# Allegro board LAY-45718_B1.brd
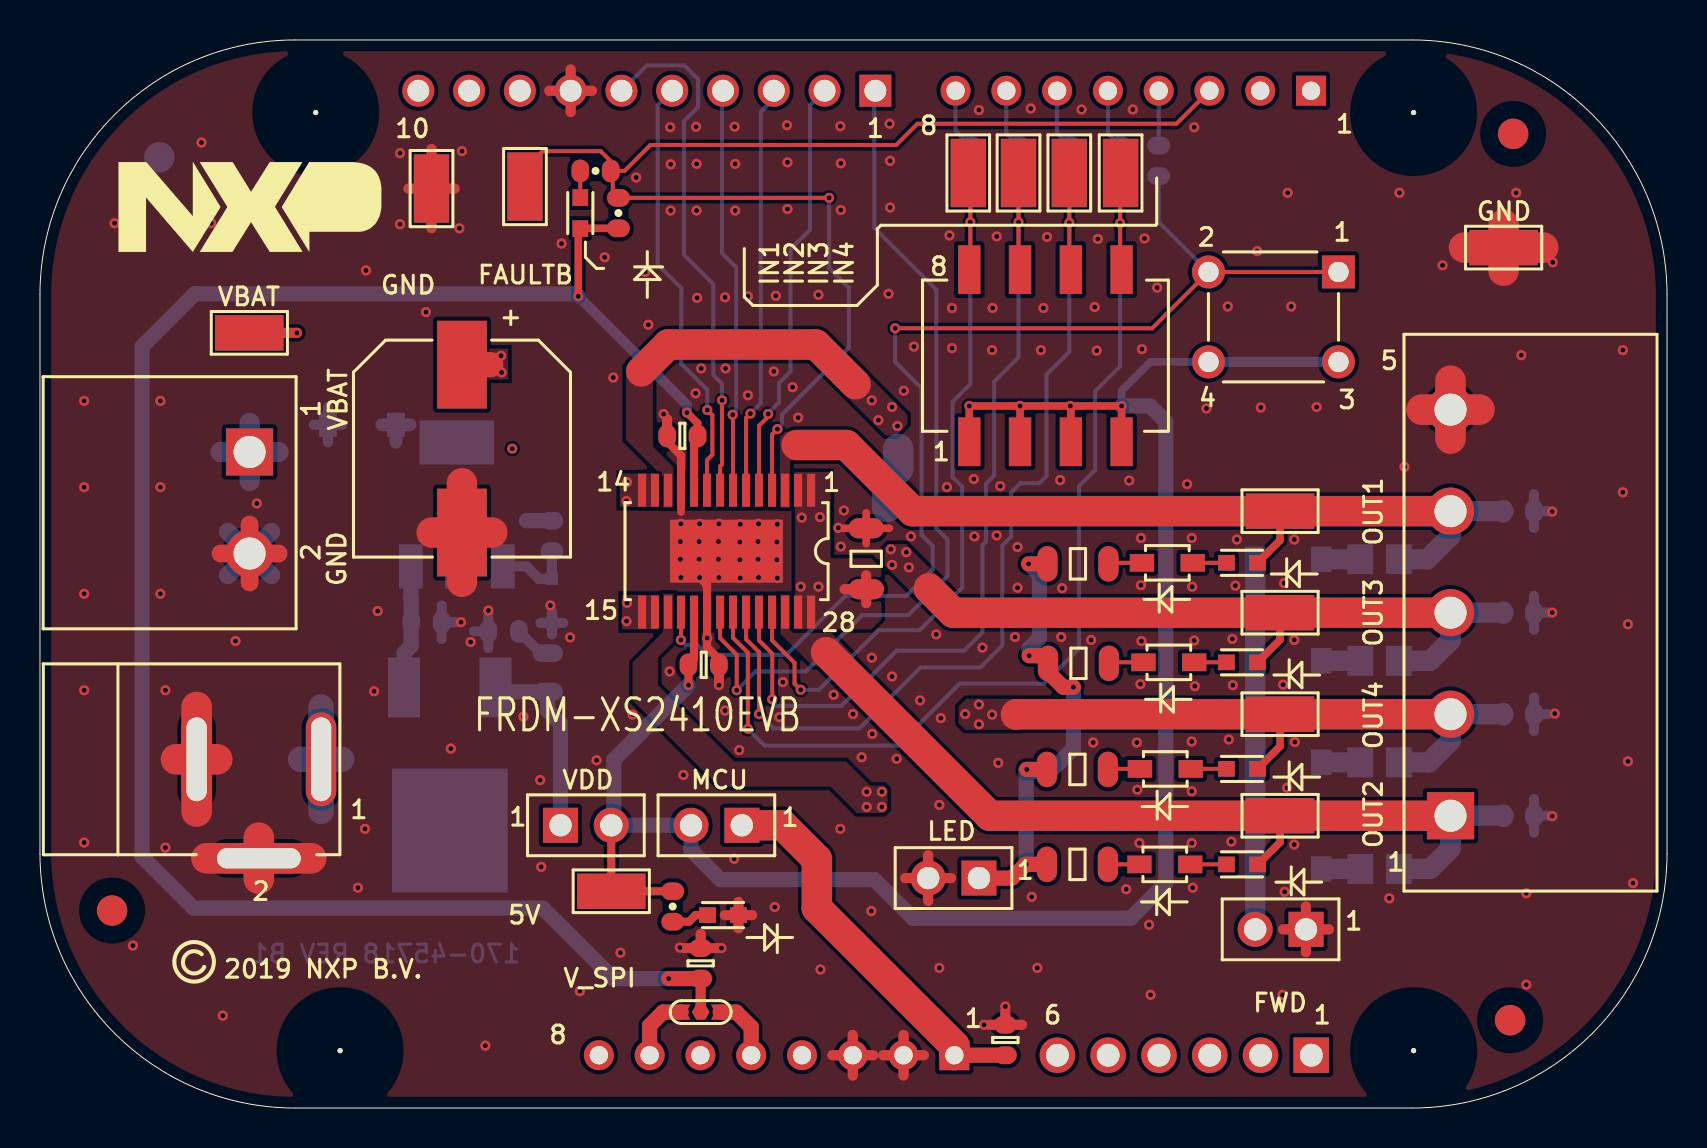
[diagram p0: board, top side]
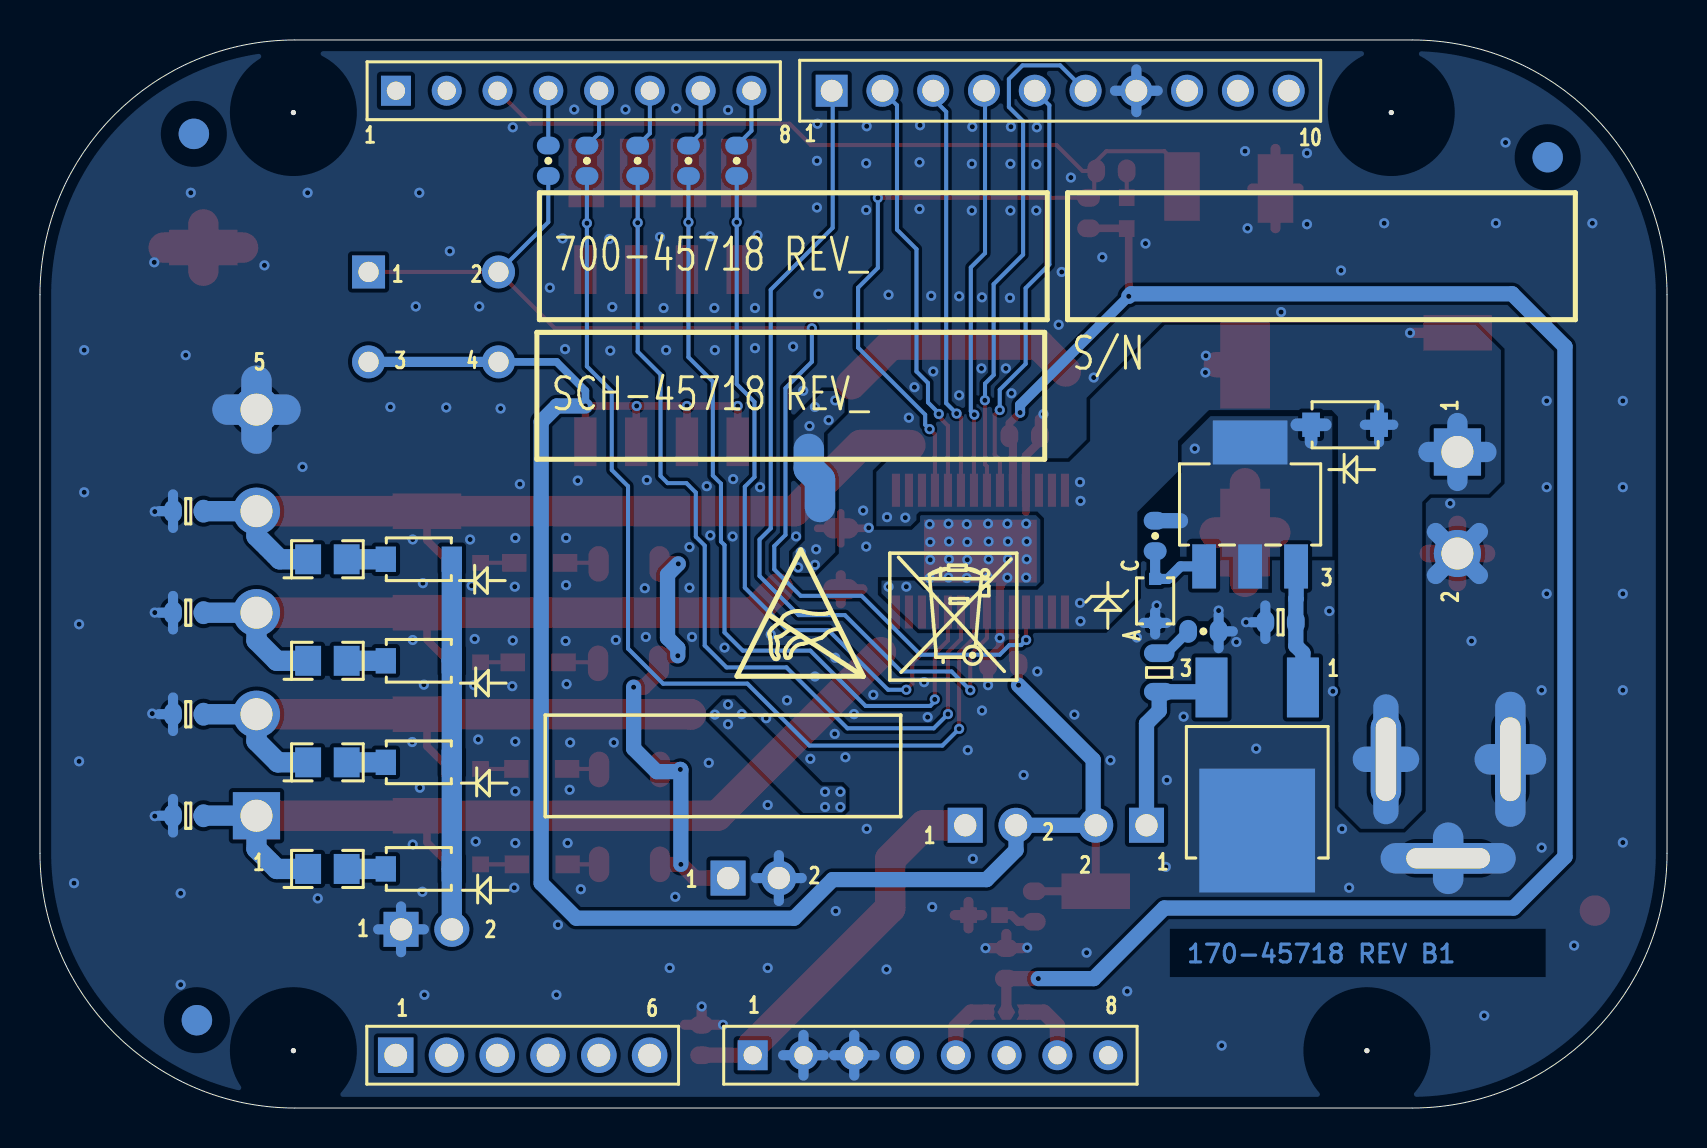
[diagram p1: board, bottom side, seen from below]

Outline 81.38 x 53.44 mm; copper layers: TOP, BOTTOM. Coordinates in mm from the lower left corner of the outline.
Outline path: 0,40.69 arc(3.73,49.71) 12.75,53.44 68.63,53.44 arc(77.65,49.71) 81.38,40.69 81.38,12.75 arc(77.65,3.73) 68.63,0 12.75,0 arc(3.73,3.73) 0,12.75 0,40.69

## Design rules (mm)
constraint set DEFAULT: min track width 0.127
net group POWER: nets 5V AGND OUT1 OUT2 V_MCU V_SPI VOUT_LDO

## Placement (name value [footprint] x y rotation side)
C1  0.1uF  [CC1206_OV]  41.33 27.48 90 top
C2  100UF  [CAP_10DIA_10P5]  21.11 32.99 270 top
C3  0.1uF  [CC0603_OV]  32.13 33.63 180 top
C4  0.1uF  [CC0603_OV]  33.2 22.17 0 top
C5  0.01uF  [CC0603_OV]  73.96 29.86 0 bottom
C6  0.33UF  [CC0603_OV]  19.33 24.31 0 bottom
C7  10UF  [CC0805_OV]  25.4 21.79 90 bottom
C8  0.01uF  [CC0603_OV]  73.96 14.62 0 bottom
C9  0.01uF  [CC0603_OV]  73.96 24.78 0 bottom
C10  0.01uF  [CC0603_OV]  73.96 19.7 0 bottom
C11  0.1uF  [CC0603_OV]  33.05 7.24 90 top
C12  0.1uF  [CC0603_OV]  48.29 3.4 90 top
D1  CMMR1U-02  [SOD-123F]  16.1 34.19 0 bottom
D2  RF071M2STR  [SOD123]  62.43 27.46 180 bottom
D3  RF071M2STR  [SOD123]  62.43 11.96 180 bottom
D4  RF071M2STR  [SOD123]  62.43 22.38 180 bottom
D5  RF071M2STR  [SOD123]  62.43 17.3 180 bottom
D6  GDZ15B-E3-08  [SOD323_B]  25.6 25.37 270 bottom
D7  RED  [LED_0603]  27.03 44.78 90 top
D8  LED GREEN  [LED_0603]  60.12 12.19 180 top
D9  LED GREEN  [LED_0603]  60.12 27.28 180 top
D10  LED GREEN  [LED_0603]  60.12 22.3 180 top
D11  LED GREEN  [LED_0603]  60.12 16.97 180 top
D12  LED GREEN  [LED_0603]  34.16 9.65 0 top
D13  1PS76SB70  [SOD323]  56.39 27.28 270 top
D14  1PS76SB70  [SOD323]  56.26 12.19 270 top
D15  1PS76SB70  [SOD323]  56.46 22.3 270 top
D16  1PS76SB70  [SOD323]  56.29 16.97 270 top
J3  CON_1X2  [CON2_5P08_12P26X12_RA_TH]  10.48 32.83 270 top
J4  OSTOQ055451  [CON5_5P08_27P5X12_RA_TH]  70.55 14.62 90 top
J5  DC_POWER_JACK  [CONN_DC_POWER_3P]  14.06 17.45 270 top
J8  HDR 1X8  [HDR1X8_2P54_TH]  63.58 50.9 90 bottom
J9  HDR 1X8  [HDR1X8_2P54_TH]  45.73 2.64 90 bottom
J10  HDR 1X10  [HDR_1X10_100_TH]  41.78 50.9 90 bottom
J11  HDR1X2  [HDR1X2_5P48X2P69]  63.32 8.94 180 top
J12  HDR1X2  [HDR1X2_5P48X2P69]  35.1 14.15 180 top
J13  HDR1X2  [HDR1X2_5P48X2P69]  26.04 14.15 0 top
J14  HDR1X2  [HDR1X2_5P48X2P69]  46.96 11.51 180 top
JP1  HDR 1X6  [HDR106_B]  63.59 2.64 90 bottom
NOREF  -  [unnamed]  3.61 9.88 0 top
NOREF#2  -  [#2]  44.42 11.51 0 top
NOREF#3  -  [#2]  -378.12 187.91 0 top
NOREF#4  -  [#2]  32.07 4.8 0 top
NOREF#5  -  [#2]  18.92 50.9 0 top
NOREF#6  -  [#2]  80.7 23.33 0 top
NOREF#7  -  [#2]  42.05 15.49 90 top
NOREF#8  -  [#2]  64.79 10.29 0 top
NOREF#9  -  [#2]  70.55 14.62 0 top
NOREF#10  -  [#2]  32.56 14.15 0 top
NOREF#11  -  [#2]  68.63 0.05 90 top
NOREF#12  -  [#2]  25.6 24.27 90 top
NOREF#13  -  [#2]  39.24 50.9 0 top
NOREF#14  -  [#2]  36.57 15.49 0 top
NOREF#15  -  [#2]  28.3 26.35 90 top
NOREF#16  -  [#2]  70.55 14.62 90 top
NOREF#17  -  [#2]  0.33 36.42 90 top
NOREF#18  -  [#2]  -13.94 -50.83 0 top
NOREF#19  -  [#2]  7.71 7.29 0 top
NOREF#20  -  [#2]  21.11 28.79 90 top
NOREF#21  -  [#2]  10.48 32.83 90 top
NOREF#22  -  [#2]  43.2 23.86 90 top
NOREF#23  -  [#2]  26.04 14.15 0 top
NOREF#24  -  [#2]  0.33 48.72 0 top
NOREF#25  -  [#2]  70.55 14.62 90 top
NOREF#26  -  [#2]  53.91 12.85 90 top
NOREF#27  -  [#2]  32.07 4.8 0 top
NOREF#28  -  [#2]  48.43 12.85 0 top
NOREF#29  -  [#2]  60.78 8.94 0 top
NOREF#30  -  [#2]  70.27 10.29 90 top
NOREF#31  -  [#2]  -404.15 -337.24 0 top
NOREF#32  -  [#2]  3.94 42.84 0 top
NOREF#33  -  [#2]  43.2 23.86 0 top
NOREF#34  -  [#2]  10.48 27.75 90 top
NOREF#35  -  [#2]  80.7 11.03 90 top
NOREF#36  -  [#2]  70.55 34.94 90 top
NOREF#37  -  [#2]  -12.74 -34.06 0 top
NOREF#38  -  [#2]  24.57 12.8 0 top
NOREF#39  -  [#2]  0.33 48.72 0 top
NOREF#40  -  [#2]  70.55 34.94 0 top
NOREF#41  -  [#2]  26.35 26.35 0 top
NOREF#42  -  [#2]  30.05 12.8 90 top
NOREF#43  -  [unnamed]  73.69 48.74 0 top
NOREF#44  -  [unnamed]  73.53 4.39 0 top
NOREF#45  -  [#2]  0.05 53.39 0 top
NOREF#46  -  [#2]  56.11 14.58 180 bottom
NOREF#47  -  [unnamed]  73.69 48.74 180 bottom
NOREF#48  -  [unnamed]  5.97 47.57 180 bottom
NOREF#49  -  [#2]  38.87 21.41 180 bottom
NOREF#50  -  [#2]  56.53 32.46 180 bottom
NOREF#51  -  [unnamed]  68.71 2.87 180 bottom
NOREF#52  -  [unnamed]  73.53 4.39 180 bottom
NOREF#53  -  [#2]  29.98 39.45 180 bottom
NOREF#54  -  [unnamed]  13.79 49.81 180 bottom
NOREF#55  -  [unnamed]  15.01 2.87 180 bottom
NOREF#56  -  [unnamed]  68.71 49.81 180 bottom
NOREF#57  -  [#2]  29.73 24.97 180 bottom
NOREF#58  -  [#2]  56.4 39.45 180 bottom
Q1  FZT692B  [SOT223]  20.85 30.2 180 bottom
R1  10K  [RC0603_OV]  25.6 28.63 270 bottom
R2  1.0K  [RC0603_OV]  31.65 10.08 270 top
R3  1.0K  [RC0603_OV]  27.79 46.89 0 top
R4  10K  [RC0603_OV]  55.96 47.4 270 bottom
R5  10K  [RC0603_OV]  54.03 47.4 270 bottom
R6  4.99K  [RC1206_OV]  51.92 27.23 180 top
R7  4.99K  [RC1206_OV]  51.89 12.19 180 top
R8  4.99K  [RC1206_OV]  51.94 22.25 180 top
R9  4.99K  [RC1206_OV]  51.89 16.94 180 top
R10  10K  [RC0603_OV]  51.49 47.4 270 bottom
R11  10K  [RC0603_OV]  48.95 47.4 270 bottom
R12  10K  [RC0603_OV]  46.53 47.4 270 bottom
R13  10K  [RC0603_OV]  28.93 44.78 90 top
R14  3 PIN 0402 JUMPER  [3PIN_0402_SOLDER_BLOB_JUMPER]  33.05 4.8 0 top
R15  0  [RC0603_OV]  23.19 23.85 180 bottom
SH1  SOLDER SHORT  [SH0805]  67.01 27.46 180 bottom
SH2  SOLDER SHORT  [SH0805]  67.01 11.96 180 bottom
SH3  SOLDER SHORT  [SH0805]  67.01 22.38 180 bottom
SH4  SOLDER SHORT  [SH0805]  67.01 17.3 180 bottom
SW1  TL1105AF100Q  [SW4_6X6_TH]  64.95 41.83 180 top
SW2  SW_DIP-4/SM  [DIP-SMT4]  50.29 37.64 90 top
TP1  TESTLOOP  [TESTPOINT_135_070MIL]  62.03 29.86 0 top
TP2  TESTLOOP  [TESTPOINT_135_070MIL]  62.03 14.62 0 top
TP3  TESTLOOP  [TESTPOINT_135_070MIL]  62.03 24.78 0 top
TP4  TESTLOOP  [TESTPOINT_135_070MIL]  62.03 19.7 0 top
TP5  TESTLOOP  [TESTPOINT_135_070MIL]  46.43 46.79 90 top
TP6  TESTLOOP  [TESTPOINT_135_070MIL]  19.58 46.01 90 top
TP7  TESTLOOP  [TESTPOINT_135_070MIL]  73.21 43.05 0 top
TP8  TESTLOOP  [TESTPOINT_135_070MIL]  10.47 38.79 0 top
TP9  TESTLOOP  [TESTPOINT_135_070MIL]  48.95 46.79 90 top
TP10  TESTLOOP  [TESTPOINT_135_070MIL]  24.26 46.11 90 top
TP11  TESTLOOP  [TESTPOINT_135_070MIL]  51.49 46.79 90 top
TP12  TESTLOOP  [TESTPOINT_135_070MIL]  28.57 10.85 0 top
TP13  TESTLOOP  [TESTPOINT_135_070MIL]  54.05 46.79 90 top
U1  MC33XS2410EL  [TSSOP28_TAB124X222]  34.34 27.86 270 top
U2  LP2950CP  [DPAK_CASE_369C-01]  20.5 15.16 0 bottom

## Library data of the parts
C1 C3-C12 = CAP_NP
C2 = CAP_POL
D1-D5 = DIODE
D6 = ZDIODE
D7-D12 = LED
D13-D16 = DIODE_SCHTKY
J3 = CONN_PLUG_1X2_M
J4 = CONN_HDR_5X1
J5 = DC_POWER_JACK_3
J8 J9 = CONN_HDR_8X1
J10 = HDR-1X10
J11-J14 = CONN_HDR_2X1
JP1 = CONN_PLUG_1X6_M
Q1 = TRAN_NPN_SOT223
R1-R13 R15 = RES
R14 = 3_Pad_Solder_Blob_Jumper
SH1-SH4 = RES_SHORT-2
SW1 = SW_PB_ESW
SW2 = SW_DIP-4_SM
TP1-TP13 = TESTLOOP
U1 = MC33XS4210_28P
U2 = MC7805

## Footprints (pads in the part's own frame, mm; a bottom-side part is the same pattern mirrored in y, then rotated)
3PIN_0402_SOLDER_BLOB_JUMPER
  custom 0.191x0.191 smd: 1(0,0) 2(0.978,0) 3(-0.978,0)
CAP_10DIA_10P5
  rect 4.394x2.489 smd: 1(-4.2,0) 2(4.2,0)
CC0603_OV
  oval 0.889x1.143 smd: 1(-0.762,0) 2(0.762,0)
CC0805_OV
  oval 0.889x1.524 smd: 1(-0.965,0) 2(0.965,0)
CC1206_OV
  oval 1.016x1.778 smd: 1(-1.524,0) 2(1.524,0)
CON2_5P08_12P26X12_RA_TH
  rect 2.362x2.362 hole 1.6: 1(0,0)
  round 2.362 hole 1.6: 2(5.08,0)
CON5_5P08_27P5X12_RA_TH
  rect 2.362x2.362 hole 1.6: 1(0,0)
  round 2.362 hole 1.6: 2(5.08,0) 3(10.16,0) 4(15.24,0) 5(20.32,0)
CONN_DC_POWER_3P
  oval 4.699x1.524 hole 4.191x1.016: 1(0,0) 3(0,-6.223)
  oval 1.524x4.699 hole 1.016x4.191: 2(4.953,-3.111)
DIP-SMT4
  rect 2.438x1.118 smd: 1(-4.305,3.81) 2(-4.305,1.27) 3(-4.305,-1.27) 4(-4.305,-3.81) 5(4.305,-3.81) 6(4.305,-1.27) 7(4.305,1.27) 8(4.305,3.81)
DPAK_CASE_369C-01
  rect 1.6x2.997 smd: 1(-2.286,-5.88) 3(2.286,-5.88)
  rect 5.791x6.198 smd: 4(0,1.283)
HDR1X2_5P48X2P69
  rect 1.753x1.753 hole 1.118: 1(0,0)
  round 1.753 hole 1.118: 2(2.54,0)
HDR1X8_2P54_TH
  rect 1.499x1.499 hole 0.914: 1(0,0)
  round 1.499 hole 0.914: 2(0,-2.54) 3(0,-5.08) 4(0,-7.62) 5(0,-10.16) 6(0,-12.7) 7(0,-15.24) 8(0,-17.78)
HDR106_B
  rect 1.778x1.778 hole 1.143: 1(0,0)
  round 1.778 hole 1.143: 2(0,-2.54) 3(0,-5.08) 4(0,-7.62) 5(0,-10.16) 6(0,-12.7)
HDR_1X10_100_TH
  rect 1.6x1.6 hole 1.092: 1(0,0)
  round 1.6 hole 1.092: 2(0,-2.54) 3(0,-5.08) 4(0,-7.62) 5(0,-10.16) 6(0,-12.7) 7(0,-15.24) 8(0,-17.78) 9(0,-20.32) 10(0,-22.86)
LED_0603
  rect 0.838x0.787 smd: A(-0.775,0) C(0.775,0)
RC0603_OV
  oval 0.889x1.143 smd: 1(-0.762,0) 2(0.762,0)
RC1206_OV
  oval 1.016x1.778 smd: 1(-1.524,0) 2(1.524,0)
SH0805
  rect 1.295x1.499 smd: 1(-0.965,0) 2(0.965,0)
SOD123
  rect 1.016x1.27 smd: A(1.651,0) C(-1.651,0)
SOD323
  rect 0.889x1.219 smd: A(0,1.27) C(0,-1.27)
SOD323_B
  rect 0.61x0.61 smd: A(1.1,0) C(-1.1,0)
SOD-123F
  rect 0.889x1.219 smd: A(-1.7,0) C(1.7,0)
SOT223
  rect 1.194x2.21 smd: 1(-2.3,-3.1) 2(0,-3.1) 3(2.3,-3.1)
  rect 3.734x2.21 smd: 4(0,3.1)
SW4_6X6_TH
  rect 1.651x1.651 hole 1.016: 1(0,0)
  round 1.651 hole 1.016: 2(6.5,0) 3(0,4.5) 4(6.5,4.5)
TESTPOINT_135_070MIL
  rect 3.429x1.778 smd: 1(0,0)
TSSOP28_TAB124X222
  rect 1.651x0.406 smd: 1(-3.048,4.227) 2(-3.048,3.576) 3(-3.048,2.926) 4(-3.048,2.276) 5(-3.048,1.626) 6(-3.048,0.975) 7(-3.048,0.325) 8(-3.048,-0.325) 9(-3.048,-0.975) 10(-3.048,-1.626) 11(-3.048,-2.276) 12(-3.048,-2.926) 13(-3.048,-3.576) 14(-3.048,-4.227) 15(3.048,-4.227) 16(3.048,-3.576) 17(3.048,-2.926) 18(3.048,-2.276) 19(3.048,-1.626) 20(3.048,-0.975) 21(3.048,-0.325) 22(3.048,0.325) 23(3.048,0.975) 24(3.048,1.626) 25(3.048,2.276) 26(3.048,2.926) 27(3.048,3.576) 28(3.048,4.227)
  rect 3.15x5.639 smd: 29(0,0)
unnamed
  round 1.524 smd: (0,0)

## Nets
5V: C4.1 J12.2 J13.2 R2.1 SW1.3 SW1.4(B2) SW2.1 SW2.2 SW2.3 SW2.4 TP12.1(PIN1) U1.19
AGND: C1.2 C2.2 C3.2 C4.2 C5.2 C6.2 C8.2 C9.2 C10.2 C11.2 C12.2 D6.A D12.C(CATHODE) J3.2 J4.5 J5.2 J5.3 J9.2 J9.3 J10.7 J11.1 J14.2 R15.2 TP6.1(PIN1) TP7.1(PIN1) U1.11 U1.20 U1.29 U2.4
VBAT: C1.1 C2.1 D1.A J3.1 J5.1 TP8.1(PIN1) U1.1 U1.2 U1.13 U1.14 U1.15 U1.16 U1.27 U1.28
CLOCK: J10.2 U1.5
FAULTB: J8.3 R3.2 R13.2 TP10.1(PIN1) U1.4
FRDM_IN1: J8.8 R12.1
FRDM_IN2: J8.7 R11.1
FRDM_IN3: J8.6 R10.1
FRDM_IN4: J8.5 R5.1
FRDM_LHM: J8.4 R4.1
IN1: R12.2 SW2.8 TP5.1(PIN1) U1.25
IN2: R11.2 SW2.7 TP9.1(PIN1) U1.24
IN3: R10.2 SW2.6 TP11.1(PIN1) U1.23
IN4: R5.2 SW2.5(B4) TP13.1(PIN1) U1.22
LHM: R4.2 SW1.1 SW1.2 U1.18
OUT1: C5.1 D9.A J4.4 SH1.1 TP1.1(PIN1) U1.3
OUT2: C8.1 D8.A J4.1 SH2.1 TP2.1(PIN1) U1.26
OUT3: C9.1 D10.A J4.3 SH3.1 TP3.1(PIN1) U1.12
OUT4: C10.1 D11.A J4.2 SH4.1 TP4.1(PIN1) U1.17
RESETB: J10.1 U1.21
SPI0_CLK: J10.6 U1.8
SPI0_CSB: J10.3 U1.6
SPI0_MISO: J10.5 U1.9
SPI0_MOSI: J10.4 U1.7
V_MCU: C12.1 J9.1 J12.1
V_SPI: C3.1 C11.1 D7.A R13.1 R14.1 U1.10(VSPI)
VOUT_LDO: C6.1 Q1.3(EMITTER) U2.1
N18288430: J9.5 R14.2
N18288522: D1.C(CATHODE) Q1.2 Q1.4 R1.1
N18288583: D6.C(CATHODE) Q1.1 R1.2
N18288585: D2.C(CATHODE) SH1.2
N18288587: D3.C(CATHODE) SH2.2
N18288662: D2.A D3.A D4.A D5.A J11.2
N18289047: C7.1 J13.1 U2.3(OUT)
N18289088: D12.A R2.2
N18289158: D9.C(CATHODE) D13.A
N18289160: D8.C(CATHODE) D14.A
N18289162: D10.C(CATHODE) D15.A
N18289164: D11.C(CATHODE) D16.A
N18289215: C7.2 R15.1
N18289308: D13.C R6.1
N18289310: D14.C R7.1
N18289312: D15.C R8.1
N18289314: D16.C R9.1
N18289449: J14.1 R6.2 R7.2 R8.2 R9.2
N18304925: D7.C(CATHODE) R3.1
N18308854: J9.7 R14.3
N18313687: D4.C(CATHODE) SH3.2
N18313700: D5.C(CATHODE) SH4.2

Pads without a net: J8 1 2; J9 4 6 8; J10 8 9 10; JP1 1 2 3 4 5 6

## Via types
v1: diameter 0.508, hole 0.254, TOP to BOTTOM, 271 vias
v2: diameter 0.508, hole 0.257, TOP to BOTTOM, 24 vias

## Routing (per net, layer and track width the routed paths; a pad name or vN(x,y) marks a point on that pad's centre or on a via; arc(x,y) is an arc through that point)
5V: length 102.5
  TOP w0.381: SW2.2 v1(49.02,35.13) ; v1(49.02,35.13) v1(51.54,35.13) ; v1(49.02,35.13) v1(46.48,35.13) SW2.1 ; v1(51.54,35.13) 51.56,35.1 SW2.3 ; v1(51.54,35.13) v1(54.1,35.13) SW2.4
  TOP w0.406: U1.19 32.72,22.45 C4.1 v1(32.44,21.16) ; J13.2 TP12.1 R2.1
  BOTTOM w0.381: v1(54.1,35.13) 54.1,35.89 55.55,37.33 SW1.4
  BOTTOM w0.508: SW1.3 SW1.4
  BOTTOM w0.762: v1(32.44,21.16) 28.7,17.42 28.7,14.27 J13.2 J12.2 32.56,12.9 34.04,11.43 41.73,11.43 43.66,9.5 54.56,9.5 56.31,11.25 56.31,34.34 55.52,35.13 v1(54.1,35.13)
AGND: length 154.9
  TOP w0.381: 41.33,28.23 C1.2 ; C1.2 42.48,29.01 ; C1.2 41.33,29.78 ; C1.2 40.17,29.01 ; U1.11 32.06,29.82
  TOP w0.406: v2(32.99,26.54) 33.37,26.17 33.32,26.13 33.37,26.09 U1.20 33.37,23.06 33.96,22.46 C4.2 ; U1.11 32.06,32.65 31.37,33.34 C3.2 ; 32.06,29.25 v2(32.05,29.24)
  TOP w0.508: D12.C 34.94,10.31 ; D12.C 35.62,9.65 ; D12.C 34.25,9.65 ; D12.C 34.94,8.99 ; J11.1 64.47,8.94 ; J11.1 62.18,8.94 ; J11.1 63.32,7.8 ; J11.1 63.32,10.08 ; TP6.1 20.74,46.01 ; TP6.1 19.58,47.99 ; TP6.1 18.43,46.01 ; TP6.1 19.58,44.02 ; 40.65,1.63 J9.3 ; J9.3 41.67,2.64 ; J9.3 40.65,3.66 ; J9.3 39.64,2.64 ; 42.18,2.64 J9.2 ; J9.2 44.21,2.64 ; J9.2 43.19,1.63 ; J9.2 43.19,3.66 ; C11.2 33.05,8.71 ; C11.2 33.88,8 ; C11.2 32.21,8 ; 47.45,4.17 C12.2 ; C12.2 48.29,4.88 ; C12.2 49.12,4.17 ; 26.54,49.83 J10.7 ; J10.7 27.61,50.9 ; J10.7 25.48,50.9 ; J10.7 26.54,51.97 ; 44.42,10.36 J14.2 ; J14.2 45.57,11.51 ; J14.2 44.42,12.65 ; J14.2 43.28,11.51 ; C3.2 31.37,34.47 ; 33.96,21.34 C4.2
  TOP w0.889: 9.04,27.75 J3.2 ; J3.2 10.48,26.3 ; J3.2 11.93,27.75 ; J3.2 10.48,29.19
  TOP w1.524: 10.95,11.47 J5.2 ; J5.2 8.33,12.5 ; J5.2 13.56,12.5 ; J5.2 10.95,13.53 ; 19.6,28.79 C2.2 ; C2.2 22.62,28.79 ; C2.2 21.11,31.26 ; C2.2 21.11,26.33 ; 6.81,17.45 J5.3 ; J5.3 7.84,20.07 ; J5.3 7.84,14.83 ; J5.3 8.87,17.45 ; 70.55,33.5 J4.5 ; J4.5 72,34.94 ; J4.5 70.55,36.39 ; J4.5 69.1,34.94 ; 73.21,41.9 TP7.1 ; TP7.1 73.21,44.21 ; TP7.1 75.19,43.05 ; TP7.1 71.23,43.05
  BOTTOM w0.508: C10.2 75.44,19.7 ; C10.2 74.73,20.54 ; C10.2 74.73,18.87 ; R15.2 22.43,24.69 ; R15.2 22.43,23.01 ; R15.2 21.72,23.85 ; J14.2 45.57,11.51 ; J14.2 43.28,11.51 ; J14.2 44.42,12.65 ; J14.2 44.42,10.36 ; 26.54,49.83 J10.7 ; J10.7 27.61,50.9 ; J10.7 25.48,50.9 ; J10.7 26.54,51.97 ; J11.1 64.47,8.94 ; J11.1 62.18,8.94 ; J11.1 63.32,10.08 ; J11.1 63.32,7.8 ; 74.73,13.79 C8.2 ; C8.2 74.73,15.46 ; C8.2 75.44,14.62 ; 74.73,29.03 C5.2 ; C5.2 75.44,29.86 ; C5.2 74.73,30.7 ; 20.09,23.47 C6.2 ; C6.2 20.8,24.31 ; C6.2 20.09,25.15 ; 39.64,2.64 J9.3 ; J9.3 40.65,3.66 ; J9.3 40.65,1.63 ; J9.3 41.67,2.64 ; 25.6,23.7 D6.A ; D6.A 25.6,24.85 ; D6.A 26.18,24.27 ; D6.A 25.03,24.27 ; 43.19,1.63 J9.2 ; J9.2 43.19,3.66 ; J9.2 42.18,2.64 ; J9.2 44.21,2.64 ; C9.2 75.44,24.78 ; C9.2 74.73,25.62 ; C9.2 74.73,23.95
  BOTTOM w0.889: J3.2 11.57,26.66 ; J3.2 9.4,26.66 ; J3.2 11.57,28.83 ; J3.2 9.4,28.83
  BOTTOM w1.524: 7.84,14.83 J5.3 ; J5.3 7.84,20.07 ; J5.3 6.81,17.45 ; J5.3 8.87,17.45 ; J4.5 72,34.94 ; J4.5 69.1,34.94 ; J4.5 70.55,36.39 ; J4.5 70.55,33.5 ; 10.95,11.47 J5.2 ; J5.2 13.56,12.5 ; J5.2 8.33,12.5 ; J5.2 10.95,13.53
  vias: v1(2.21,35.38) v1(2.21,31.06) v1(2.21,25.73) v1(2.21,20.9) v1(2.21,13.28) v1(3.73,44.27) v1(4.65,8.13) v1(6.02,35.38) v1(6.02,31.06) v1(6.02,25.73) v1(6.27,20.9) v1(6.27,13.03) v1(8.08,48.31) v1(8.56,44.27) v1(9.14,4.62) v1(9.78,23.37) v1(10.85,30.25) v1(14.15,44.27) v1(15.9,11.02) v1(16.26,13.97) v1(16.31,41.91) v1(16.71,20.85) v1(16.89,24.87) v1(18.01,47.78) v1(18.01,44.22) v1(19.3,39.83) v1(20.55,17.98) v1(20.98,44.02) v1(21.06,24.31) v1(21.11,47.88) v1(21.54,23.32) v1(22.28,3.12) v1(22.43,24.89) v1(24.18,19.58) v1(25.02,16.41) v1(25.07,12.07) v1(25.53,25.15) v1(26.09,43.26) v1(26.52,23.55) v1(27,5.84) v1(27.84,17.4) v1(28.24,42.57) v1(28.68,36.55) v1(29.03,7.77) v1(29.64,19.69) v1(29.82,46.56) v1(30.28,41.83) v1(30.43,39.19) v1(31.19,34.72) v1(31.52,49.07) v1(31.55,47.22) v1(31.55,44.91) v1(31.5,21.84) v1(32,8.03) v1(32.18,16.66) v1(32.82,49.1) v1(32.84,47.24) v1(32.84,44.91) v1(32.79,35.76) v1(32.87,40.54) v1(33.07,37.01) v1(33.38,23.52) v1(33.96,21.16) v1(34.09,8) v1(34.26,40.56) v1(34.29,37.01) v1(34.26,19.89) v1(34.75,49.1) v1(34.72,12.47) v1(34.77,47.24) v1(34.77,44.91) v1(34.98,17.91) v1(35.41,40.61) v1(35.41,35.66) v1(36.7,36.86) v1(36.75,10.06) v1(36.8,40.64) v1(36.98,19.56) v1(37.16,21.31) v1(37.36,49.17) v1(37.39,47.32) v1(37.39,44.98) v1(37.64,36.07) v1(37.92,34.54) v1(38.94,40.69) v1(39.04,6.93) v1(39.7,20.68) v1(39.93,29.03) v1(40.03,49.12) v1(40.06,47.27) v1(40.06,44.93) v1(40.06,28.09) v1(40.03,13.97) v1(40.21,29.9) v1(40.67,19.71) v1(41.1,17.55) v1(41.61,22.53) v1(41.63,18.72) v1(41.58,9.86) v1(42.44,40.74) v1(42.49,49.25) v1(42.52,47.4) v1(42.52,45.06) v1(42.62,21.59) v1(42.85,17.48) v1(43.21,35.89) v1(43.56,28.6) v1(43.71,38.1) v1(44.02,20.4) v1(44.83,23.7) v1(45.06,19.51) v1(44.98,15.16) v1(44.98,7.01) v1(45.36,31.06) v1(45.49,43.66) v1(45.62,40.03) v1(45.62,38.02) v1(46.71,31.47) v1(46.74,28.6) v1(46.96,49.94) v1(47.14,23.04) v1(47.22,4.17) v1(47.65,40.03) v1(47.62,37.92) v1(47.85,43.61) v1(47.85,28.65) v1(47.93,17.27) v1(48.03,31.12) v1(48.29,5.08) v1(48.77,23.57) v1(48.9,28.07) v1(48.9,26.04) v1(49.56,50.01) v1(49.61,10.57) v1(49.89,7.01) v1(50.06,37.92) v1(50.19,40.03) v1(50.37,43.59) v1(51.03,31.42) v1(51.13,26.01) v1(51.08,23.57) v1(52.1,49.96) v1(52.58,23.42) v1(52.76,40.08) v1(52.68,18.29) v1(52.86,37.9) v1(52.91,43.48) v1(54.33,10.95) v1(54.48,31.39) v1(54.66,49.96) v1(54.86,18.29) v1(54.89,15.93) v1(55.04,21.21) v1(54.99,13.26) v1(55.12,37.97) v1(55.07,28.52) v1(55.07,26.16) v1(55.09,23.37) v1(55.25,43.51) v1(55.47,9.17) v1(55.55,5.66) v1(55.88,41.05) v1(57.38,31.22) v1(57.61,28.52) v1(57.63,26.09) v1(57.61,18.34) v1(57.61,15.85) v1(57.61,13.26) v1(57.66,11.02) v1(57.73,49.07) v1(57.73,23.39) v1(57.76,21.11) v1(58.34,35) v1(59.41,40.11) v1(59.46,18.44) v1(59.64,23.47) v1(59.59,13.34) v1(59.66,21.16) v1(59.79,26.14) v1(59.87,28.45) v1(60.88,42.88) v1(61.06,35.05) v1(62.15,5.66) v1(62.23,26.26) v1(62.18,21.18) v1(62.26,10.82) v1(62.41,45.8) v1(62.38,16.03) v1(62.59,40.11) v1(62.74,28.45) v1(62.74,23.42) v1(62.74,13.18) v1(62.76,18.31) v1(63.86,35.08) v1(67.49,10.49) v1(68,45.8) v1(68.25,32.08) v1(70.15,42.16) v1(73.84,45.8) v1(74.09,37.67) v1(74.35,10.74) v1(74.35,6.17) v1(75.64,29.84) v1(75.64,24.79) v1(75.64,14.61) v1(75.67,42.32) v1(75.77,19.74) v1(79.17,37.92) v1(79.17,30.81) v1(79.43,24.21) v1(79.43,17.35) v1(79.68,11.25) v2(32.03,28.35) v2(32.03,27.46) v2(32.05,26.54) v2(32.99,29.24) v2(32.97,28.35) v2(32.97,27.46) v2(33.96,29.24) v2(33.93,28.35) v2(33.93,27.46) v2(33.96,26.54) v2(35.03,29.21) v2(35,28.32) v2(35,27.43) v2(35.03,26.52) v2(35.94,29.24) v2(35.92,28.35) v2(35.92,27.46) v2(35.94,26.54) v2(36.86,28.32) v2(36.86,27.43) v2(36.88,29.21) v2(36.88,26.52)
VBAT: length 22.6
  TOP w0.508: TP8.1 v1(12.85,38.79) ; 40.25,25.96 C1.1 ; C1.1 41.33,26.66 ; C1.1 41.33,25.26
  TOP w1.27: C2.1 22.54,37.19
  BOTTOM w0.508: D1.A 15.12,34.19 ; D1.A 14.4,35.07 ; D1.A 13.69,34.19 ; D1.A 14.4,33.31
  BOTTOM w1.016: 10.48,31.38 J3.1 ; J3.1 10.48,34.27 ; J3.1 9.04,32.83 ; J3.1 11.93,32.83
  BOTTOM w1.27: 14.06,14.83 J5.1 ; J5.1 14.06,20.07 ; J5.1 15.09,17.45 ; J5.1 13.03,17.45
  vias: v1(23.06,37.64) v1(23.09,36.8) v1(29.34,30.38) v1(29.34,24.36) v1(29.36,31.32) v1(29.36,25.27) v1(38.05,26.09) v1(38.1,29.54) v1(38.94,26.09) v1(39.01,29.57)
CLOCK: length 21.3
  TOP w0.203: v1(36.42,34.73) 36.42,34.59 35.97,34.14 U1.5
  BOTTOM w0.203: v1(36.42,34.73) 36.42,34.73 36.45,34.76 36.45,34.79 36.96,35.31 36.96,36.28 37.54,36.86 37.54,42.98 38.52,43.95 38.52,50.17 J10.2
FAULTB: length 66.6
  TOP w0.203: v1(39.47,45.54) R13.2 28.65,45.82 28.65,46.79 R3.2 ; J8.3 56.85,49.25 43.89,49.25 42.82,48.18 30.53,48.18 29.24,46.89 R3.2 ; R3.2 28.63,46.96 28.63,47.29 28.04,47.88 25.15,47.88 24.26,46.99 TP10.1 ; v1(36.89,33.97) 36.62,33.7 U1.4
  BOTTOM w0.203: v1(36.89,33.97) 37.11,34.19 37.11,34.69 40.46,38.05 40.46,41.05 39.47,42.04 v1(39.47,45.54)
FRDM_IN1: length 3
  BOTTOM w0.203: R12.1 45.8,48.89 J8.8
FRDM_IN2: length 3
  BOTTOM w0.203: R11.1 48.34,48.77 J8.7
FRDM_IN3: length 3
  BOTTOM w0.203: R10.1 50.88,48.77 J8.6
FRDM_IN4: length 3
  BOTTOM w0.203: R5.1 53.42,48.76 53.42,48.79 53.42,48.79 J8.5
FRDM_LHM: length 2.7
  BOTTOM w0.203: J8.4 R4.1
IN1: length 40.8
  TOP w0.203: U1.25 36.62,23.4 37.74,22.28 37.74,21.23 v1(38.05,20.93) ; SW2.8 46.49,41.94 46.53,41.97 v1(46.53,44.32) 46.53,46.69 TP5.1
  BOTTOM w0.203: R12.2 v1(46.53,44.32) 46.53,36.22 45.64,35.33 45.64,31.57 46.13,31.09 46.13,26.04 44,23.91 41.94,23.91 38.96,20.93 v1(38.05,20.93)
IN2: length 45.3
  TOP w0.203: SW2.7 48.95,42.02 v1(48.95,44.32) TP9.1 ; U1.24 35.97,23.39 36.63,22.73 v1(36.63,20.45)
  BOTTOM w0.203: R11.2 v1(48.95,44.32) 48.95,37.57 47.73,36.35 47.73,31.65 47.32,31.24 47.32,28.35 47.14,28.17 47.14,23.8 46.23,22.89 42.85,22.89 40.08,20.12 36.86,20.12 36.63,20.35 v1(36.63,20.45)
IN3: length 49.9
  TOP w0.203: TP11.1 v1(51.49,44.3) 51.49,42.02 SW2.6 ; v1(35.97,19.71) 35.97,22.81 35.32,23.46 U1.23
  BOTTOM w0.203: v1(35.97,19.71) 36.68,19 41,19 44.04,22.05 47.04,22.05 48.13,23.14 48.13,28.14 48.58,28.59 48.58,30.8 49.05,31.27 49.99,31.27 50.34,31.62 50.34,36.7 51.49,37.85 v1(51.49,44.3) R10.2
IN4: length 54.4
  TOP w0.203: v1(35.41,18.97) 35.41,22.78 34.67,23.53 U1.22 ; TP13.1 54.03,46.76 v1(54.03,44.27) 54.03,42.02 SW2.5
  BOTTOM w0.203: R5.2 v1(54.03,44.27) 54.03,37.11 52.78,35.86 52.78,31.93 51.97,31.12 51.97,22.99 50.22,21.23 46,21.23 42.9,18.14 36.25,18.14 v1(35.41,18.97)
LHM: length 58.1
  TOP w0.203: v1(32.05,23.42) 32.06,23.43 U1.18 ; SW1.1 SW1.2 55.63,39.01 v1(42.77,39.01)
  BOTTOM w0.203: v1(42.77,39.01) 42.77,37.34 44.09,36.02 44.09,28.68 44.65,28.12 44.65,26.95 43.33,25.63 40.28,25.63 37.34,22.68 33.38,22.68 32.89,23.16 32.31,23.16 v1(32.05,23.42) ; R4.2 55.96,44.33 SW1.2
OUT1: length 44.1
  TOP w0.381: D9.A 62.03,28.41 TP1.1
  TOP w1.524: J4.4 TP1.1 43.64,29.86 40.34,33.17 37.85,33.17
  BOTTOM w1.016: SH1.1 69.39,27.46 70.55,28.62 J4.4 C5.1
OUT2: length 44.8
  TOP w0.381: D8.A 60.92,12.19 62.03,13.3 TP2.1
  TOP w1.524: 39.32,22.81 47.5,14.62 TP2.1 J4.1
  BOTTOM w1.016: SH2.1 69.54,11.96 70.55,12.98 J4.1 70.56,14.63 73.2,14.63 C8.1
OUT3: length 51.8
  TOP w0.381: TP3.1 62.03,23.43 D10.A
  TOP w1.524: 30.07,36.86 31.42,38.2 38.81,38.2 40.8,36.22 ; J4.3 TP3.1 45.67,24.78 44.46,26
  BOTTOM w1.016: SH3.1 69.54,22.38 70.55,23.39 J4.3 C9.1
  BOTTOM w1.524: 42.37,30.07 42.37,31.45 42.93,32 42.93,32.98
  vias: v1(41.61,35.41) v1(41.94,34.42) v1(42.56,27.96) v1(42.62,35.08) v1(42.62,27.18) v1(42.89,34.12) v1(43.33,27.81) v1(43.46,27.05)
OUT4: length 32
  TOP w0.381: D11.A 62.03,18.1 TP4.1
  TOP w1.524: 48.82,19.69 48.84,19.7 TP4.1 J4.2
  BOTTOM w1.016: SH4.1 69.49,17.3 70.55,18.36 J4.2 C10.1
  vias: v1(41.35,15.82) v1(41.35,15.06) v1(42.11,15.82) v1(42.11,15.06) v1(46.28,19.71) v1(46.96,20.19) v1(46.96,19.2) v1(47.62,19.69)
RESETB: length 43
  TOP w0.203: v1(34.85,20.9) 34.85,22.68 34.02,23.52 U1.21
  BOTTOM w0.203: J10.1 41.73,50.85 41.73,44.04 44.83,40.94 44.83,29.01 45.39,28.45 45.39,26.62 43.43,24.66 41.12,24.66 38.3,21.84 35.79,21.84 v1(34.85,20.9)
SPI0_CLK: length 26.3
  TOP w0.203: v1(34.12,35.41) 34.11,35.41 34.11,32.2 34.02,32.11 U1.8
  BOTTOM w0.203: v1(34.12,35.41) 34.11,35.42 34.11,36.25 33.68,36.68 33.68,41.22 32.21,42.7 32.21,49.38 32.92,50.09 32.92,51.49 32.23,52.17 30.35,52.17 J10.6
SPI0_CSB: length 20.6
  TOP w0.203: v1(35.53,34.75) 35.32,34.53 U1.6
  BOTTOM w0.203: v1(35.53,34.75) 36.06,35.27 36.06,49.85 36.7,50.5 J10.3
SPI0_MISO: length 21.5
  TOP w0.203: v1(33.38,34.92) 33.63,34.67 33.63,32.69 33.37,32.43 U1.9
  BOTTOM w0.203: v1(33.38,34.92) 33.38,35.94 32.08,37.24 32.08,41.02 30.9,42.21 30.9,50.17 J10.5
SPI0_MOSI: length 20.4
  TOP w0.203: v1(34.65,34.69) 34.67,34.67 U1.7
  BOTTOM w0.203: v1(34.65,34.69) 34.82,34.87 34.82,42.06 34.11,42.77 34.11,50.85 J10.4
V_MCU: length 19.7
  TOP w0.762: J9.1 C12.1
  TOP w1.524: J9.1 45.73,3.12 38.86,10 38.86,12.45 37.16,14.15 J12.1
V_SPI: length 98.2
  TOP w0.381: C3.1 32.89,34.26 v1(32.36,34.8) ; v1(26.92,40.61) 26.92,43.9 D7.A 27.04,44.02 R13.1
  TOP w0.406: C3.1 32.72,33.45 U1.10
  TOP w0.508: R14.1 C11.1
  TOP w0.762: C11.1 v1(31.45,6.48)
  BOTTOM w0.508: v1(26.92,40.61) 32.36,35.18 v1(32.36,34.8)
  BOTTOM w0.762: v1(31.45,6.48) 28.68,6.48 25.15,10.01 7.67,10.01 5.11,12.57 5.11,38.1 7.75,40.74 26.8,40.74 v1(26.92,40.61)
VOUT_LDO: length 6.2
  BOTTOM w0.762: U2.1 18.21,22.77 18.57,23.13 C6.1 18.57,25.47 18.55,25.49 Q1.3
N18288430: length 3.3
  TOP w0.762: R14.2 34.82,4.8 35.57,4.05 J9.5
N18288522: length 3.6
  BOTTOM w0.635: D1.C 18.52,34.19 ; D1.C 17.09,34.19 ; D1.C 17.8,33.31
  BOTTOM w0.762: R1.1 24.33,29.39
  vias: v1(23.62,32.99)
N18288583: length 4.1
  BOTTOM w0.508: Q1.1 24.33,27.1 24.96,26.47 D6.C R1.2
N18288585: length 2
  BOTTOM w1.016: D2.C SH1.2
N18288587: length 2
  BOTTOM w1.016: D3.C SH2.2
N18288662: length 18.5
  BOTTOM w1.016: D2.A D4.A D5.A D3.A J11.2
N18289047: length 9.6
  BOTTOM w0.762: J13.1 26.04,19.24 25.4,19.88 C7.1 23,20.83 U2.3
N18289088: length 1.9
  TOP w0.406: D12.A 32.79,9.65 32.46,9.32 R2.2
N18289158: length 1.7
  TOP w0.203: D9.C D13.A
N18289160: length 1.8
  TOP w0.203: D8.C D14.A
N18289162: length 1.6
  TOP w0.203: D10.C D15.A
N18289164: length 1.8
  TOP w0.203: D11.C D16.A
N18289215: length 1.9
  BOTTOM w0.508: R15.1 25.04,22.76 C7.2
N18289308: length 1.7
  TOP w0.203: D13.C 53.49,27.28 R6.1
N18289310: length 1.6
  TOP w0.203: D14.C R7.1
N18289312: length 1.7
  TOP w0.203: R8.1 53.52,22.3 D15.C
N18289314: length 1.6
  TOP w0.203: D16.C 53.44,16.97 R9.1
N18289449: length 24.5
  TOP w0.762: R7.2 v1(49.33,12.19) 49.3,12.19 48.62,11.51 J14.1 ; R9.2 v1(49.35,16.94) ; v1(49.48,22.63) 50.04,22.63 R8.2 50.42,21.82 51.18,21.06 v1(51.69,21.06) ; R6.2 v1(49.45,27.23)
  BOTTOM w0.762: v1(49.33,12.19) 49.33,16.92 v1(49.35,16.94) 49.46,16.83 50.54,16.83 51.69,17.99 v1(51.69,21.06) ; v1(49.48,22.63) 49.48,23.01 49.99,23.53 49.99,26.69 v1(49.45,27.23)
N18304925: length 1.3
  TOP w0.203: R3.1 D7.C
N18308854: length 3.3
  TOP w0.762: R14.3 31.17,4.8 30.49,4.13 J9.7
N18313687: length 2
  BOTTOM w1.016: D4.C SH3.2
N18313700: length 2
  BOTTOM w1.016: D5.C SH4.2

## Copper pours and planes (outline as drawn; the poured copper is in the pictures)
AGND on TOP: 0.56,40.69 4.13,49.31 12.75,52.88 68.63,52.88 77.25,49.31 80.82,40.69 80.82,12.75 77.25,4.13 68.63,0.56 12.75,0.56 4.13,4.13 0.56,12.75
AGND on BOTTOM: 0.56,40.69 4.13,49.31 12.75,52.88 68.63,52.88 77.25,49.31 80.82,40.69 80.82,12.75 77.25,4.13 68.63,0.56 12.75,0.56 4.13,4.13 0.56,12.75 ; 3 cut-outs
VBAT on TOP: 37.77,31.83 39.55,31.83 39.55,27.51 41.58,27.51 42.09,27 42.09,24.46 41.58,23.95 37.77,23.95
VBAT on TOP: 29.11,25.68 29.11,23.95 30.94,23.95 30.94,25.68
VBAT on TOP: 19.89,38 19.89,36.45 23.42,36.45 23.42,38
VBAT on TOP: 29.01,31.75 29.01,30.07 30.94,30.07 30.94,31.75
VBAT on BOTTOM: 12.24,14.91 12.24,30.33 11.86,30.71 8.92,30.71 8.31,31.32 8.31,37.92 9.58,39.19 25.12,39.19 28.85,35.46 28.85,33.38 29.9,32.33 39.04,32.33 39.55,31.83 39.55,29.11 37.85,29.11 37.54,29.41 37.54,29.69 37.39,29.84 31.5,29.84 31.17,29.51 31.17,26.26 31.5,25.93 37.19,25.93 37.64,26.39 39.29,26.39 39.29,25.76 37.4,23.94 30.91,23.95 30.91,23.95 28.12,23.95 26.49,25.58 26.49,29.82 24.46,31.85 24.46,33.38 22.91,34.92 16.77,34.92 16.46,34.59 16.43,15.09 15.32,13.97 13.18,13.97
OUT1 on TOP: 37.01,30.05 37.52,30.05 37.52,32.33 37.8,32.66 39.01,32.66 39.01,33.83 37.24,33.83 37.01,33.6
OUT2 on TOP: 37.64,23.77 39.57,23.77 40.67,22.68 40.11,22.12 38.63,22.12 37.03,23.72 37.03,25.68 37.52,25.68 37.52,23.9
OUT3 on TOP: 31.17,30.05 31.67,30.05 31.67,32.08 30.66,33.1 30.66,37.19 29.39,37.19 29.31,37.11 29.31,33.43 31.17,31.57
OUT3 on TOP: 40.26,35.69 42.29,33.66 42.82,33.66 43.38,34.21 43.38,34.7 41.33,36.75
OUT3 on TOP: 42.24,27.15 44.4,24.99 45.47,26.06 43.31,28.22 42.44,28.22 42.24,28.02
OUT3 on BOTTOM: 41.14,34.81 42.16,33.78 42.16,31.93 43.69,31.93 43.69,34.39 42.2,35.88 41.59,35.88 41.14,35.42
OUT3 on BOTTOM: 42.65,26.77 43.56,26.77 43.74,26.95 43.74,27.79 43.13,28.4 43.13,30.3 41.61,30.3 41.61,27.81
OUT4 on TOP: 31.17,25.73 31.67,25.73 31.67,23.32 30.91,22.56 30.91,21.16 34.72,17.35 40.31,17.35 41.53,16.13 42.21,16.13 42.39,15.95 42.39,14.96 42.19,14.76 40.87,14.76 39.55,16.08 33.96,16.08 29.64,20.4 29.64,22.3 31.17,23.83
OUT4 on TOP: 45.95,19.25 46.28,18.92 48.97,18.92 48.97,20.47 46.33,20.47 45.95,20.09
OUT4 on BOTTOM: 46.66,20.47 47.22,20.47 47.9,19.79 47.9,19.46 43.21,14.76 41.27,14.76 41.07,14.96 41.07,15.93 41.27,16.13 42.32,16.13
N18288522 on BOTTOM: 16.74,34.62 16.74,27.58 19.94,27.58 19.94,25.96 21.72,25.96 21.72,27.58 24.36,27.58 24.36,33.1 22.83,34.62

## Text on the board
BOTTOM: 170-45718 REV B1 | 5 OF 8 | L2_SS
Board Geometry/Soldermask Bottom: 6 OF 8 | SECONDARY SOLDERMASK
Ref Des/Silkscreen Bottom: 7 OF 8 | SECONDARY SILKSCREEN
User.Comments: 1 OF 1 | TEST PROBE | 1/1 | 1 | 2
TOP: 4 OF 8 | L1_PS
Board Geometry/Soldermask Top: 3 OF 8 | PRIMARY SOLDERMASK
Ref Des/Silkscreen Top: V_SPI | GND | VBAT | 2 OF 8 | PRIMARY SILKSCREEN | FRDM-XS2410EVB
XSECTION_CHART: Location           RefDes      Net 1         Net 2 | (2047.00 358.00)   SH2       OUT2       &  N18288587 | (2047.00 568.00)   SH4       OUT4       &  N18313700 | (2047.00 968.00)   SH1       OUT1       &  N18288585 | (2047.00 768.00)   SH3       OUT3       &  N18313687 | 22 | 8 | 19 | 16 | *  SURFACE - AIR 0 MIL | *  DIELECTRIC - DRY_FILM_MASK 0.8 MIL | L1 TOP CONDUCTOR - 2OZ_COPPER 2.8 MIL | *  DIELECTRIC - FR-4 56.5 MIL | L2 BOTTOM CONDUCTOR - 2OZ_COPPER 2.8 MIL | DESIGN CROSS SECTION CHART | ___________________________ | TOTAL THICKNESS 63.7 MIL | 1-2
DIMENSION: PRIMARY DATUM | GRID ORIGIN
BODY_CENTER: 1 OF 8 | PASTEMASK TOP
DISPLAY_TOP: 8 OF 8 | SECONDARY PASTEMASK
User.15: 2
User.16: MARIUS TEODORESCU | 05-07-19 | D.A. | B1 | SILKSCREEN UPDATE
User.20: FIGURE | FINISHED_SIZE | 10.0 | 10.1 | 36.0 | 40.0 | 43.0 | 44.0 | 45.0 | 63.0 | 125.0 | 165.0x40.0 | ROTATION | - | 90.000 | 0.000 | DRILL CHART: TOP to BOTTOM | ALL UNITS ARE IN MILS | TOLERANCE_DRILL | +0.0/-10.0 | +0.0/-10.1 | +3.0/-3.0 | +2.0/-2.0 | TOLERANCE_TRAVEL | PLATED | NON-PLATED | QTY | 271 | 24 | 16 | 4 | 10 | 8 | 6 | 7 | 2 | 1
